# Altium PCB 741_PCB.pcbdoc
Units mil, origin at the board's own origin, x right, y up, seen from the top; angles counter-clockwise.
Board outline 3300 x 2250 mil, 2 copper layers (Top Layer, Bottom Layer); 36 components, 26 nets, 111 pads, 19 vias.
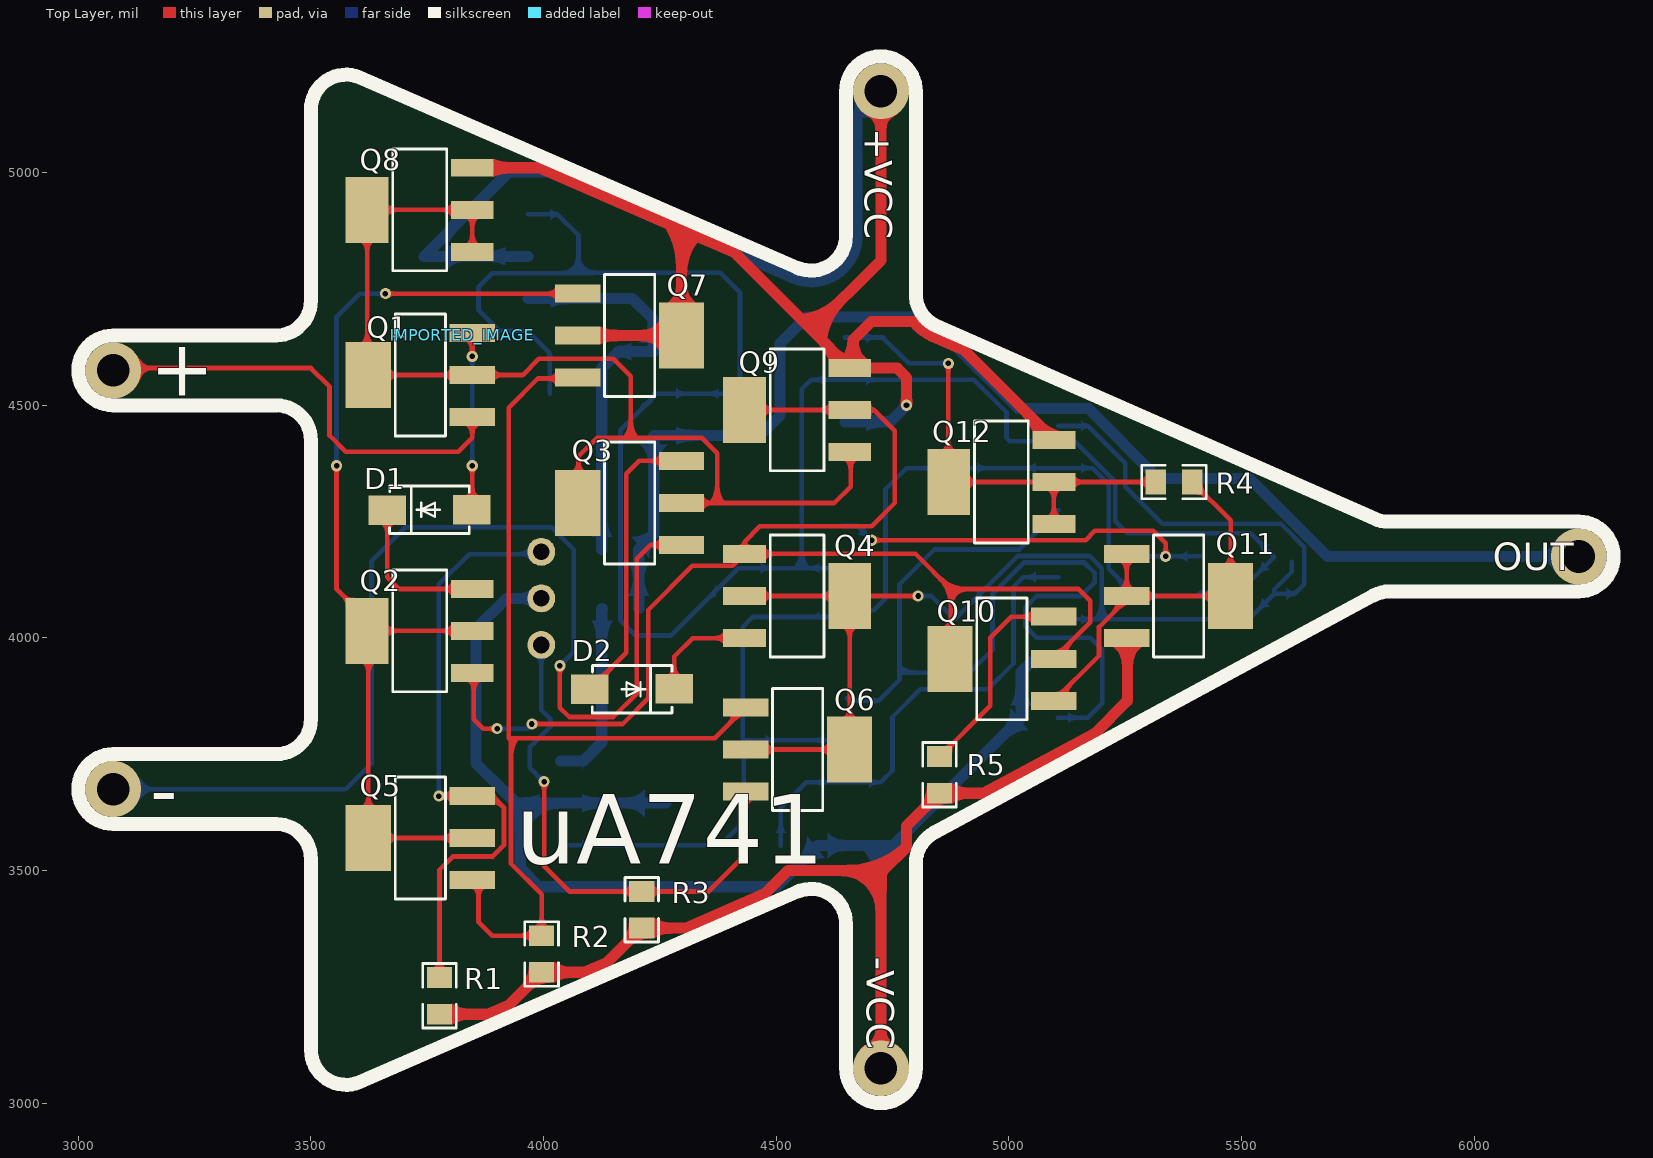
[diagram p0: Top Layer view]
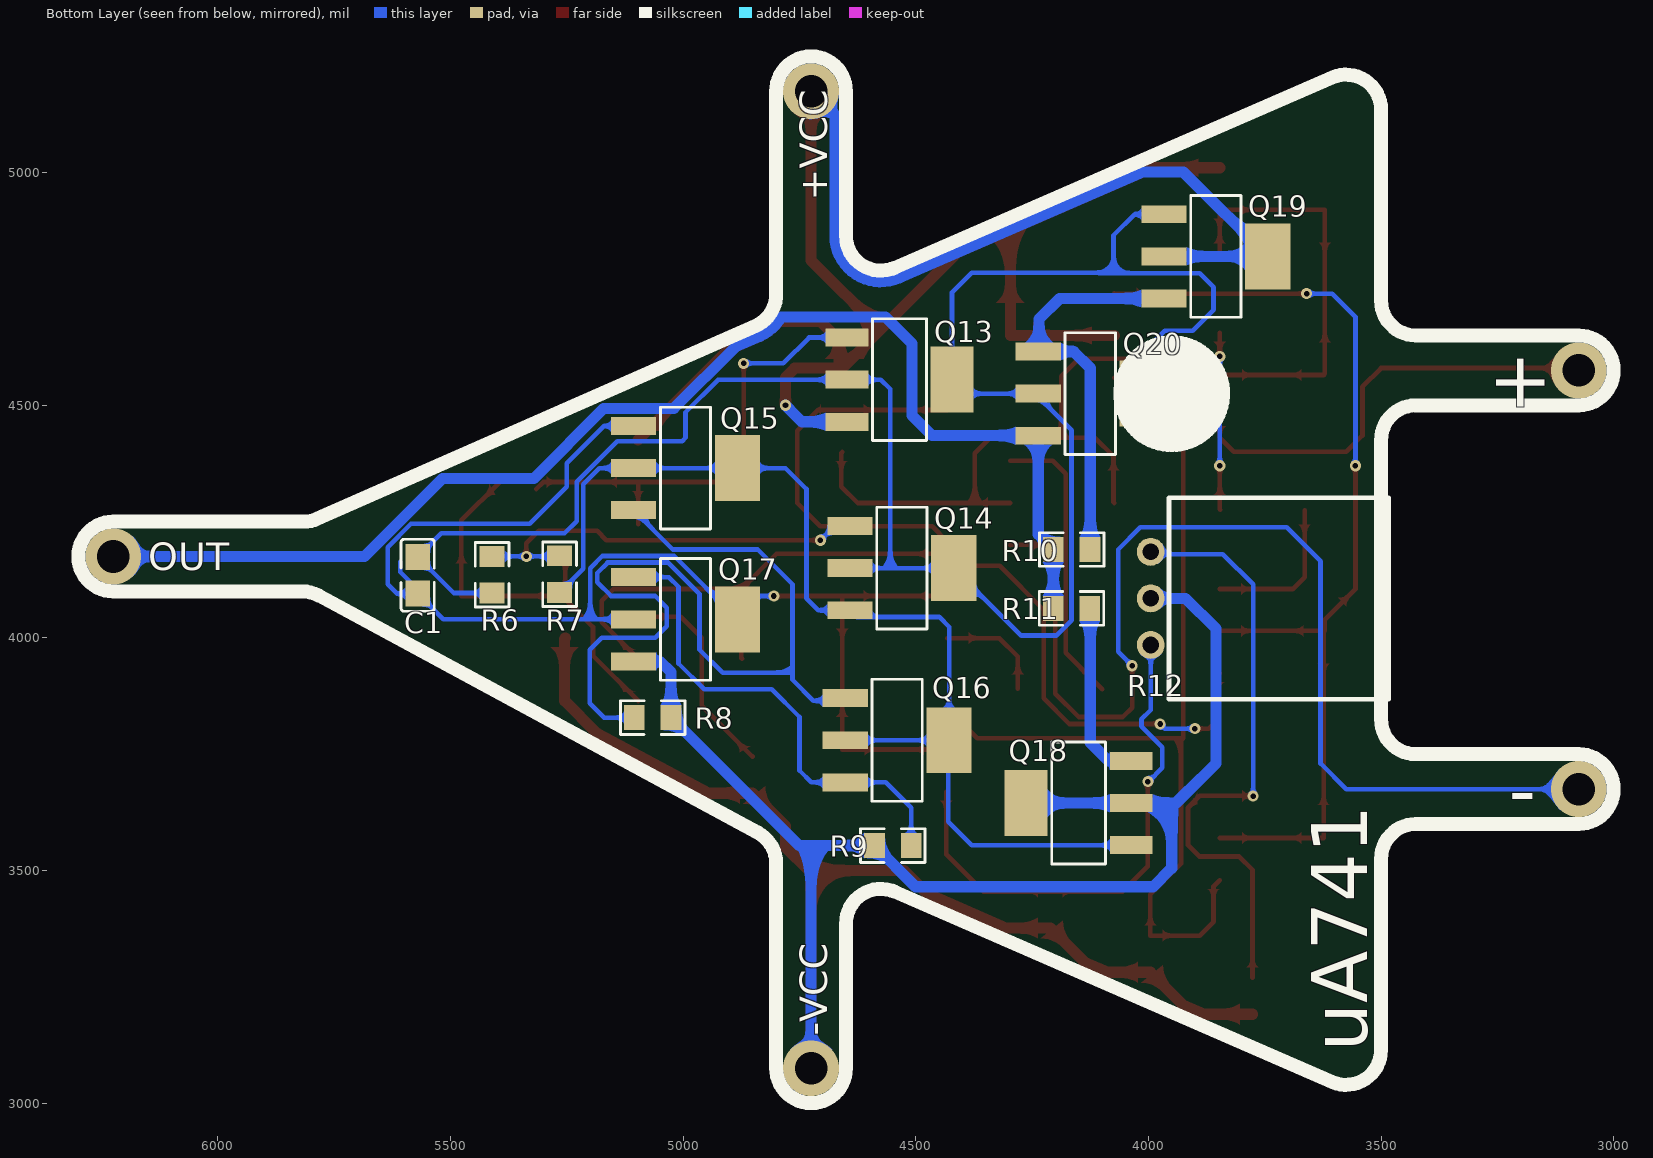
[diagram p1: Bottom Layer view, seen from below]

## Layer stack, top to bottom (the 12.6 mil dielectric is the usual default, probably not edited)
Top Layer: signal copper (thickness not stored)
Dielectric: dielectric 12.6, FR-4, Dk 4.8
Bottom Layer: signal copper (thickness not stored)

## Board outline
4844.79,4670.29 5785.57,4256.35 ccw(c5815.77,4325) 5815.77,4250 6225,4250 cw(c6225,4175) 6300,4175 cw(c6225,4175) 6225,4100 5818.96,4100 ccw(c5818.96,4025) 5783.32,4090.99 4839.36,3581.26 ccw(c4875,3515.26) 4800,3515.26 4800,3075 cw(c4725,3075) 4725,3000 cw(c4725,3075) 4650,3075 4650,3385.61 ccw(c4575,3385.61) 4545.1,3454.39 3604.91,3045.61 cw(c3575.01,3114.39) 3500.01,3114.39 3500.01,3525 ccw(c3425.01,3525) 3425.01,3600 3075,3600 cw(c3075,3675) 3000,3675 cw(c3075,3675) 3075,3750 3425,3750 ccw(c3425,3825) 3500,3825 3500,4425 ccw(c3425,4425) 3425,4500 3075,4500 cw(c3075,4575) 3000,4575 cw(c3075,4575) 3075,4650 3425,4650 ccw(c3425,4725) 3500,4725 3500,5135.61 cw(c3575,5135.61) 3604.9,5204.39 4545.1,4795.61 ccw(c4575,4864.39) 4650,4864.39 4650,5175 cw(c4725,5175) 4725,5250 cw(c4725,5175) 4800,5175 4800,4738.94 ccw(c4875,4738.94)

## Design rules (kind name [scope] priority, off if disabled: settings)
BoardOutlineClearance copperThickness1oz [All] p0: genericclearance=10 ignorepadtopadclearanceinfootprint=FALSE except(0: Arc-SplitContinuation Track-SplitContinuation SMDPad-SplitContinuation THPad-SplitContinuation Via-SplitContinuation Fill-SplitContinuation Poly-SplitContinuation Region-SplitContinuation Text-SplitContinuation; 6: Track-CutoutEdge SMDPad-CutoutEdge THPad-CutoutEdge Via-CutoutEdge Region-CutoutEdge; 11.8: Track-OutlineEdge SMDPad-OutlineEdge THPad-OutlineEdge Via-OutlineEdge Fill-OutlineEdge Region-OutlineEdge Poly-OutlineEdge Text-OutlineEdge Fill-CutoutEdge)
BoardOutlineClearance copperThickness2oz [All] p0: genericclearance=10 ignorepadtopadclearanceinfootprint=FALSE except(0: Arc-SplitContinuation Track-SplitContinuation SMDPad-SplitContinuation THPad-SplitContinuation Via-SplitContinuation Fill-SplitContinuation Poly-SplitContinuation Region-SplitContinuation Text-SplitContinuation; 6: Track-CutoutEdge SMDPad-CutoutEdge THPad-CutoutEdge Via-CutoutEdge Region-CutoutEdge; 11.8: Track-OutlineEdge SMDPad-OutlineEdge THPad-OutlineEdge Via-OutlineEdge Fill-OutlineEdge Region-OutlineEdge Poly-OutlineEdge Text-OutlineEdge Fill-CutoutEdge)
Clearance copperThickness1oz [(InNet('IN+') OR InNet('$1N519') OR InNet('$1N1834') OR InNet('$1N2546') OR InNet('$1N1895') OR InNet('$1N1839') OR InNet('$1N1919') OR InNet('$1N1914') OR InNet('OFFSET2') OR InNet('$1N1844') OR InNet('IN-') OR InNet('OFFSET1') OR InNet('VCC+') OR InNet('$1N2407') OR InNet('$1N2205') OR InNet('VCC-') OR InNet('$1N2269') OR InNet('$1N2565') OR InNet('$1N2520') OR InNet('$1N2487') OR InNet('$1N2501') OR InNet('$1N2714') OR InNet('OUT') OR InNet('$1N3714') OR InNet('$1N3732') OR InNet('$1N2679'))] p1: gap=7 ignorepadtopadclearanceinfootprint=FALSE except(4: Track-Track; 6: Track-SMDPad SMDPad-SMDPad Track-THPad SMDPad-THPad THPad-THPad Track-Via SMDPad-Via THPad-Via Via-Via SMDPad-Fill THPad-Fill Via-Fill Fill-Fill Track-Region SMDPad-Region THPad-Region Via-Region Region-Region Track-Poly SMDPad-Poly THPad-Poly Via-Poly Fill-Poly Region-Poly Poly-Poly Track-Text SMDPad-Text THPad-Text Via-Text Fill-Text Region-Text Poly-Text Text-Text; 6.9: Track-Hole SMDPad-Hole THPad-Hole Via-Hole Fill-Hole Region-Hole Poly-Hole Text-Hole Sheet-Hole; 11.8: Track-Fill Fill-Region Track-Sheet SMDPad-Sheet THPad-Sheet Via-Sheet Fill-Sheet Region-Sheet Poly-Sheet Text-Sheet)
Clearance copperThickness2oz [All] p1: gap=7 ignorepadtopadclearanceinfootprint=FALSE except(6: Track-SMDPad SMDPad-SMDPad Track-THPad SMDPad-THPad THPad-THPad Track-Via SMDPad-Via THPad-Via Via-Via SMDPad-Fill THPad-Fill Via-Fill Fill-Fill Track-Region SMDPad-Region THPad-Region Via-Region Region-Region Track-Poly SMDPad-Poly THPad-Poly Via-Poly Fill-Poly Region-Poly Poly-Poly Track-Text SMDPad-Text THPad-Text Via-Text Fill-Text Region-Text Poly-Text Text-Text; 6.9: Track-Hole SMDPad-Hole THPad-Hole Via-Hole Fill-Hole Region-Hole Poly-Hole Text-Hole Sheet-Hole; 8: Track-Track; 11.8: Track-Fill Fill-Region Track-Sheet SMDPad-Sheet THPad-Sheet Via-Sheet Fill-Sheet Region-Sheet Poly-Sheet Text-Sheet)
DiffPairsRouting differentialPair [All] p1: maxuncoupledlength=10 minlimit=6 maxlimit=6 mostfreqgap=6 toplayer_minwidth=5 toplayer_prefwidth=10 toplayer_maxwidth=100 bottomlayer_minwidth=5 bottomlayer_prefwidth=10 bottomlayer_maxwidth=100
PasteMaskExpansion pasteMaskExpansion [All] p1: expansion=0
PlaneConnect innerPlane [All] p1: planeconnectstyle=Relief reliefexpansion=20 reliefentries=4 reliefconductorwidth=10 reliefairgap=10
PolygonConnect copperRegion [All] p1: connectstyle=Relief reliefentries=4 reliefconductorwidth=10 polygonreliefangle="90 Angle" airgapwidth=10
RoutingVias viaSize [All] p1: viastyle="Through Hole" holewidth=12.0078 minholewidth=11.811 maxholewidth=248.0314 width=24.0158 minwidth=19.685 maxwidth=393.7008
SolderMaskExpansion solderMaskExpansion [All] p1: useseparateexpansions=TRUE expansion=2 expansionbottom=2
Width copperThickness1oz [All] p1: maxlimit=100 minlimit=5 preferedwidth=10
Width copperThickness2oz [All] p1: maxlimit=100 minlimit=8 preferedwidth=10

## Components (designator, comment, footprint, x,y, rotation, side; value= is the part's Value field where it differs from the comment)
C1 "CC0805JRNPO9BN330" C0805 5570.63,4134.57 r90 bottom
D1 "SS24_C7420362" SMA_L4.3-W2.6-LS5.0-FD 3755,4275 r180 top
D2 "SS24_C7420362" SMA_L4.3-W2.6-LS5.0-FD 4190,3890 r0 top
IMPORTED_IMAGE "IMPORTED_IMAGE" IMPORTED_IMAGE 3825,4650 r0 top
Q1 "BCP56-16_C41375109" SOT-223-4_L6.5-W3.5-P2.30-LS7.0-BR 3735,4565 r0 top
Q2 "BCP53-16_C41375110" SOT-223-3_L6.7-W3.7-P2.30-LS7.0-BR 3733.82,4015 r0 top
Q3 "BCP56-16_C41375109" SOT-223-4_L6.5-W3.5-P2.30-LS7.0-BR 4185,4290 r0 top
Q4 "BCP53-16_C41375110" SOT-223-3_L6.7-W3.7-P2.30-LS7.0-BR 4545,4090 r180 top
Q5 "BCP56-16_C41375109" SOT-223-4_L6.5-W3.5-P2.30-LS7.0-BR 3735,3570 r0 top
Q6 "BCP56-16_C41375109" SOT-223-4_L6.5-W3.5-P2.30-LS7.0-BR 4546.18,3760 r180 top
Q7 "BCP56-16_C41375109" SOT-223-4_L6.5-W3.5-P2.30-LS7.0-BR 4185,4650 r180 top
Q8 "BCP53-16_C41375110" SOT-223-3_L6.7-W3.7-P2.30-LS7.0-BR 3733.82,4920 r0 top
Q9 "BCP53-16_C41375110" SOT-223-3_L6.7-W3.7-P2.30-LS7.0-BR 4545,4490 r0 top
Q10 "BCP56-16_C41375109" SOT-223-4_L6.5-W3.5-P2.30-LS7.0-BR 4985,3955 r0 top
Q11 "BCP56-16_C41375109" SOT-223-4_L6.5-W3.5-P2.30-LS7.0-BR 5365,4090 r180 top
Q12 "BCP53-16_C41375110" SOT-223-3_L6.7-W3.7-P2.30-LS7.0-BR 4983.82,4335 r0 top
Q13 "BCP53-16_C41375110" SOT-223-3_L6.7-W3.7-P2.30-LS7.0-BR 4535,4555 r0 bottom
Q14 "BCP56-16_C41375109" SOT-223-4_L6.5-W3.5-P2.30-LS7.0-BR 4530,4150 r0 bottom
Q15 "BCP56-16_C41375109" SOT-223-4_L6.5-W3.5-P2.30-LS7.0-BR 4995,4365 r0 bottom
Q16 "BCP56-16_C41375109" SOT-223-4_L6.5-W3.5-P2.30-LS7.0-BR 4540,3780 r0 bottom
Q17 "BCP56-16_C41375109" SOT-223-4_L6.5-W3.5-P2.30-LS7.0-BR 4995,4040 r0 bottom
Q18 "BCP53-16_C41375110" SOT-223-3_L6.7-W3.7-P2.30-LS7.0-BR 4150,3645 r180 bottom
Q19 "BCP56-16_C41375109" SOT-223-4_L6.5-W3.5-P2.30-LS7.0-BR 3855,4820 r0 bottom
Q20 "BCP56-16_C41375109" SOT-223-4_L6.5-W3.5-P2.30-LS7.0-BR 4125,4525 r0 bottom
R1 "0805W8F1001T5E" R0805 3776.19,3230.62 r90 top
R2 "0805W8F5102T5E" R0805 3995.79,3320.62 r90 top
R3 "0805W8F1001T5E" R0805 4210.79,3415.62 r90 top
R4 "0805W8F3902T5E" R0805 5355,4335 r180 top
R5 "0805W8F4701T5E" R0805 4850.94,3705.62 r90 top
R6 "0805W8F4701T5E" R0805 5410.63,4135.83 r270 bottom
R7 "0805W8F7501T5E" R0805 5265.63,4137.09 r90 bottom
R8 "0805W8F5102T5E" R0805 5065.63,3828.62 r0 bottom
R9 "0805W8F510JT5E" R0805 4549.37,3553.62 r180 bottom
R10 "0805W8F2401T5E" R0805 4165,4190 r180 bottom
R11 "0805W8F510JT5E" R0805 4165.42,4063.44 r0 bottom
R12 "3296W-1-103_C48997937" 电位器 3995,3985 r90 bottom

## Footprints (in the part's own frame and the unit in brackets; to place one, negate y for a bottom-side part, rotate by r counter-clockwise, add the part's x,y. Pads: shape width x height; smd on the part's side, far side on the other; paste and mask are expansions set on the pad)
C0805 [mm]
  rect 1.41x1.35 smd: 1(-1,0) 2(1,0)
  silkscreen extent -1.96,-0.9 1.96,0.9
IMPORTED_IMAGE [mil]
R0805 [mm]
  rect 1.133x1.377 smd: 1(-1,0) 2(1,0)
  silkscreen extent -1.76,-0.92 1.76,0.92
SMA_L4.3-W2.6-LS5.0-FD [mm]
  rect 2.046x1.62 smd: 1(-2.304,-0.009) 2(2.304,0.009)
  silkscreen extent -2.17,-1.32 2.19,1.29
SOT-223-3_L6.7-W3.7-P2.30-LS7.0-BR [mm]
  rect 2.34x0.98 smd: 1(2.87,-2.3) 2(2.87,0) 3(2.87,2.3)
  rect 2.34x3.6 smd: 4(-2.87,0)
  silkscreen extent -1.47,-3.33 1.47,3.33
SOT-223-4_L6.5-W3.5-P2.30-LS7.0-BR [mm]
  rect 2.47x0.98 smd: 1(2.835,-2.3) 2(2.835,0) 3(2.835,2.3)
  rect 2.47x3.6 smd: 4(-2.835,0)
  silkscreen extent -1.37,-3.33 1.37,3.33
电位器 [mil]
  round 60 hole 36: 1(0,0) 2(100,0) 3(200,0)
  silkscreen extent -117,-512 317,-39

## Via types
v1: diameter 24.02, hole 12.01, Top Layer to Bottom Layer, 14 vias
v2: diameter 120, hole 70, Top Layer to Bottom Layer, 5 vias

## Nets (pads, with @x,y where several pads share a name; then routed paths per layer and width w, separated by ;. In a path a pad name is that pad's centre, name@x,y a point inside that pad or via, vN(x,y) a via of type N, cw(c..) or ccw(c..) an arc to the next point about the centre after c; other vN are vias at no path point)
$1N519: Q1.2 Q1.4 Q3.2 Q3.4 Q8.1 Q8.2 Q8.4 Q9.1 | length 2389.1
  Top Layer w10: Q8.1 Q8.2 Q8.4 3620.83,4567.56 Q1.4 Q1.2 3955,4565 3990,4600 4150,4600 4187.5,4562.5 4187.5,4432.11 4189.61,4430 ; Q3.4 4075,4291.61 4075,4390 4115,4430 4189.61,4430 ; Q3.2 4372.9,4290 ; Q9.1 4660,4397.44 4660,4325 4625,4290 4372.9,4290 ; 4189.61,4430 4340,4430 4372.9,4397.1 4372.9,4290
$1N1834: D1.1 Q1.3 | length 380.6
  Top Layer w10: D1.1 3846.61,4276.27 v1(3846.61,4370) ; v1(3846.61,4605) Q1.3
  Bottom Layer w10: v1(3846.61,4370) v1(3846.61,4605)
$1N1839: D1.2 Q2.3 | length 337.3
  Top Layer w10: D1.2 3664.3,4130.7 3690,4105 3846.26,4105 Q2.3
$1N1844: Q2.2 Q2.4 Q5.2 Q5.4 Q7.1 | length 2136.9
  Top Layer w10: v1(3555,4370) 3555,4105 3620.83,4039.17 Q2.4 ; v1(3660,4740) 4072.84,4740 Q7.1 ; Q5.2 Q5.4 3623.39,4012.44 Q2.4 ; Q2.2 Q2.4
  Bottom Layer w10: v1(3555,4370) 3555,4690 3605,4740 v1(3660,4740)
$1N1895: C1.1 Q4.2 Q4.4 Q6.2 Q6.4 Q15.1 Q17.2 Q17.4 | length 2908.2
  Top Layer w10: Q4.2 Q4.4 ; Q6.2 Q6.4 4657.99,3760.2 Q4.4 ; v1(4805,4090) Q4.4
  Bottom Layer w10: v1(4805,4090) 4833.39,4090 Q17.4 5019.37,4175.98 5174.02,4175.98 5200,4150 5200,4040.02 ; Q17.2 5200.02,4040 ; Q15.1 5169.45,4455.55 5250,4375 5250,4325 5330,4245 5585,4245 5635,4195 5635,4115 5615,4095 5570.83,4095 C1.1 ; 5608.19,4163.53 5608.19,4141.63 5570.63,4104.07 C1.1 ; 5200.02,4040 5515.43,4040 C1.1
$1N1914: D2.2 Q4.3 | length 237.3
  Top Layer w10: D2.2 4280.7,3960 4320.15,3999.45 Q4.3
$1N1919: D2.1 Q3.3 | length 626
  Top Layer w10: D2.1 4177.5,3967.84 4177.5,4352.5 4205.55,4380.55 Q3.3
$1N2205: Q10.3 R5.2 | length 455.7
  Top Layer w10: R5.2 4960,3854.05 4960,4000 5005.55,4045.55 Q10.3
$1N2269: Q12.1 Q12.2 Q12.4 Q13.1 R4.2 | length 1041.9
  Top Layer w10: v1(4870,4590) 4870,4335.83 Q12.4 Q12.2 ; Q12.1 Q12.2 ; R4.2@5315.63,4320 5300.63,4335 Q12.2
  Bottom Layer w10: Q13.1 4729.45,4645.55 4785,4590 v1(4870,4590)
$1N2407: Q10.1 Q11.1 Q11.2 Q11.4 R4.1 | length 883.3
  Top Layer w10: Q10.1 5193.78,3961.62 5193.78,4023.29 5253.39,4082.9 Q11.2 ; Q11.1 Q11.2 ; R4.1 5476.61,4252.76 Q11.4 Q11.2
$1N2487: Q15.3 Q16.1 R8.2 | length 1988.8
  Bottom Layer w10: Q16.1 4657.16,3865 4720,3865 4765,3910 4765,3920.79 ; R8.2 5170,3828.62 5200.69,3859.31 5200.69,3974.31 5175,4000 5060,4000 5035,4025 5035,4065 5060,4090 5155,4090 5185,4120 5185,4139.47 5162.5,4161.97 5031.97,4161.97 4965,4095 4965,3975 4915,3925 4769.21,3925 4765,3920.79 ; Q15.3 5022.16,4190 4840,4190 4765,4115 4765,3920.79
$1N2501: Q16.3 Q17.1 R9.2 | length 1047.3
  Bottom Layer w10: R9.2 4510,3635 4564.45,3689.45 Q16.3 4724.45,3689.45 4750,3715 4750,3830 4810,3890 4955,3890 5010,3945 5010,4110 5030.55,4130.55 Q17.1
$1N2520: Q14.3 Q15.2 Q15.4 Q16.2 Q16.4 Q18.1 R7.1 | length 2389.7
  Bottom Layer w10: Q18.1 4379.45,3554.45 4430,3605 4430,3778.39 Q16.4 ; Q16.2 Q16.4 ; R7.1 5215,4148.35 5215,4330 5180,4365 Q15.2 Q15.4 4780,4365 4735,4320 4735,4085 4709.45,4059.45 Q14.3 4627.16,4045 4450,4045 4428.39,4023.39 Q16.4
$1N2546: C1.2 Q13.2 Q13.4 Q14.2 Q14.4 Q19.1 Q20.2 Q20.4 R6.2 | length 4421.7
  Bottom Layer w10: Q19.1 4029.45,4910.55 4075,4865 4075,4783.9 ; Q20.4 4013.39,4611.61 3965,4660 3905,4660 3860,4705 3860,4753.9 3890,4783.9 4075,4783.9 ; Q14.2 4555.53,4150 ; R6.2 5493.15,4096.46 C1.2 5519.57,4225 5255,4225 5229.02,4250.98 5229.02,4335.81 5141.89,4422.93 5002.07,4422.93 4995,4430 4995,4485 4925,4555 Q13.2 4575,4555 4555,4535 4555,4150.53 4555.53,4150 ; 4075,4783.9 4075.96,4783.9 4077.06,4785 4380,4785 4422.01,4742.99 Q13.4 4392.01,4525 Q20.2 4236.61,4517.9 4165.16,4446.45 4165.16,4038.14 4198.3,4005 4273.39,4005 Q14.4 4555.53,4150
$1N2565: Q14.1 R6.1 R7.2 | length 900.8
  Top Layer w10: v1(4705,4210) 5165,4210 5185,4230 5310,4230 5336.97,4203.03 v1(5336.97,4175.2)
  Bottom Layer w10: Q14.1 4674.45,4240.55 v1(4705,4210) ; R7.2 5266.89,4175.2 v1(5336.97,4175.2) R6.1
$1N2679: Q19.3 Q20.1 R10.2 | length 873.5
  Bottom Layer w24: Q19.3 4190.55,4729.45 4235,4685 4235,4617.16 Q20.1 4160.55,4615.55 4125,4580 4125,4190.63 R10.2
$1N2714: Q18.3 R11.1 | length 393.2
  Bottom Layer w24: Q18.3 4085.55,3735.55 4125,3775 4125,4062.38 R11.1
$1N3714: Q2.1 Q4.1 Q9.2 Q9.4 Q10.2 Q10.4 | length 2931.2
  Top Layer w10: Q2.1 3850,3921.26 3850,3825 3870,3805 v1(3900,3805) ; v1(3975,3815) 4170,3815 4225,3870 4225,4060 4320,4155 4406.46,4155 Q4.1 ; Q9.4 Q9.2 4710,4490 4755,4445 4755,4290 4705,4240 4465,4240 4432.01,4207.01 Q4.1 ; Q10.4 4875,3956.61 4875,4105 ; Q10.2 5175,4033.39 5175,4080 5150,4105 4875,4105 ; Q4.1 4799.45,4180.55 4875,4105
  Bottom Layer w10: v1(3900,3805) 3965,3805 v1(3975,3815)
$1N3732: Q5.1 Q6.1 Q7.3 R2.2 | length 2119.8
  Top Layer w10: Q5.1 3860,3466.06 3860,3390 3890.01,3359.99 R2.2 3995.79,3449.21 3930,3515 3930,3779.05 3925,3784.05 ; Q7.3 4071.44,4557.5 3987.5,4557.5 3925,4495 3925,3784.05 ; Q6.1 4368.07,3784.05 3925,3784.05
IN+: Q1.1 | length 966.6
  Top Layer w10: v2(3075,4575) 3080,4580 3500,4580 3540,4540 3540,4435 3575,4400 3816.61,4400 3846.61,4430 Q1.1
IN-: Q3.1 | length 2443.2
  Top Layer w10: v1(4035,3940) 4035,3850 4055,3830 4150,3830 4200,3880 4200,4170 4230,4200 4296.06,4200 Q3.1
  Bottom Layer w10: v2(3075,3675) 3575,3675 3630,3730 3630,4165 3702.5,4237.5 4017.5,4237.5 4065,4190 4065,3970 v1(4035,3940)
OFFSET1: Q5.3 R1.2 R12.3 | length 1327.1
  Top Layer w10: v1(3775,3660) 3775.55,3660.55 Q5.3 3889.45,3660.55 3915,3635 3915,3554.94 3890.06,3530 3805,3530 3776.19,3501.19 R1.2
  Bottom Layer w10: v1(3775,3660) 3775,4115 3840,4180 3990,4180 R12.3
OFFSET2: Q6.3 R3.2 R12.1 | length 1140.5
  Top Layer w10: v1(4001.22,3691.22) 4001.22,3508.78 4055.01,3454.99 R3.2 4355,3455 4434.57,3534.57 Q6.3
  Bottom Layer w10: R12.1 3995,3845 4015,3825 4015,3810 3970,3765 3970,3720.77 3999.55,3691.22 v1(4001.22,3691.22)
OUT: Q20.3 R10.1 R11.2 | length 2778
  Bottom Layer w24: R11.2 4204.37,4063.86 R10.1 4236.61,4222.24 Q20.3 4237.16,4435 4465,4435 4508.03,4478.03 4508.03,4633.03 4565,4690 4789.16,4690 ccw(c4875,4738.94) 4835.2,4648.5 4887.93,4625.3 5020.4,4492.83 5170.85,4492.83 5321.02,4342.66 5517.06,4342.66 5684.72,4175 v2(6225,4175)
VCC+: Q7.2 Q7.4 Q8.3 Q9.3 Q12.3 Q13.3 Q19.2 Q19.4 | length 4588.1
  Top Layer w24: Q8.3 3991.02,5010.55 4299.77,4876.31 ; Q7.2 Q7.4 4296.61,4873.15 4299.77,4876.31 ; v2(4725,5175) 4725,4811.65 4575.95,4662.59 ; v1(4780,4500) 4780,4560 4760,4580 4658.54,4580 Q9.3 ; Q12.3 4904.24,4618.12 4835.2,4648.5 cw(c4875,4738.94) 4795.69,4680 4705,4680 4665,4640 4665,4587.56 Q9.3 ; 4299.77,4876.31 4410.28,4828.26 4575.95,4662.59 ; 4575.95,4662.59 Q9.3
  Bottom Layer w24: Q19.2 Q19.4 3925.08,5001.69 4011.39,5001.69 4535.6,4773.77 ccw(c4575,4864.39) 4673.81,4864.39 4673.81,5123.81 v2(4725,5175) ; Q13.3 4744.45,4464.45 v1(4780,4500)
VCC-: Q11.3 Q17.3 Q18.2 Q18.4 R1.1 R2.1 R3.1 R5.1 R8.1 R9.1 R12.2 | length 5253.2
  Top Layer w24: R1.1 3880.15,3191.25 3925.51,3210.97 R2.1 4087.15,3281.25 4137.82,3303.28 R3.1 4305.65,3376.25 4474.78,3449.78 4525,3500 4730,3500 ; v2(4725,3075) 4725,3495 4730,3500 ; Q11.3 5255,3997.84 5255,3865 5184.91,3794.91 4946.64,3666.25 R5.1 4780,3595.31 4780,3550 4730,3500
  Bottom Layer w24: R12.2 3920,4085 3855,4020 3855,3730 3940,3645 3949.88,3645 ; Q18.4 Q18.2 3949.88,3645 ; v2(4725,3075) 4725,3550.49 4721.88,3553.62 ; Q17.3 5049.45,3949.45 5026.26,3926.26 R8.1 4751.26,3553.62 4721.88,3553.62 ; 3949.88,3645 3950,3644.88 3950,3505 3990,3465 4500.12,3465 R9.1 4721.88,3553.62

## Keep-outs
Board Outline Layer:
  the board outline again, w10

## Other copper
Top Layer:
  region net $1N2407: 5471.61,4175.87 5481.61,4175.87 ccw(c5500.36,4175.87) 5489.11,4160.87 5464.11,4160.87 ccw(c5452.86,4175.87)
  region net $1N2407: 5421.97,4314.47 5419.71,4302.59 ccw(c5403.8,4281.38) 5403.8,4307.89 5416.66,4330.38 ccw(c5443.18,4330.38)
  region net $1N2407: 5412.99,4085 5412.99,4095 ccw(c5412.99,4113.75) 5427.99,4102.5 5427.99,4077.5 ccw(c5412.99,4066.25)
  region net $1N2407: 5317.01,4095 5317.01,4085 ccw(c5317.01,4066.25) 5302.01,4077.5 5302.01,4102.5 ccw(c5317.01,4113.75)
  region net $1N2565: 5331.97,4191.55 5341.97,4191.55 5342.06,4190.41 5342.32,4189.28 5343.22,4187.06 5344.51,4184.99 5345.98,4183.14 5327.97,4183.14 5329.44,4184.99 5330.72,4187.06 5331.63,4189.28 5331.88,4190.41
  region net VCC-: 5267,3944.16 5243,3944.16 ccw(c5198,3944.16) 5225,3980.16 5285,3980.16 ccw(c5312,3944.16)
  region net $1N2407: 5258.39,4146.26 5248.39,4146.26 ccw(c5229.64,4146.26) 5240.89,4161.26 5265.89,4161.26 ccw(c5277.14,4146.26)
  region net $1N2407: 5248.39,4124.29 5258.39,4124.29 ccw(c5277.14,4124.29) 5265.89,4109.29 5240.89,4109.29 ccw(c5229.64,4124.29)
  region net $1N2407: 5240.38,4062.82 5220.81,4057.39 ccw(c5198.73,4079.47) 5228.7,4070.71 5253.7,4070.71 ccw(c5262.46,4040.74)
  region net $1N2269: 5278.34,4330 5278.34,4340 ccw(c5278.34,4358.75) 5293.34,4347.5 5293.34,4322.5 ccw(c5278.34,4311.25)
  region net $1N2269: 5157.87,4340 5157.87,4330 ccw(c5157.87,4311.25) 5142.87,4322.5 5142.87,4347.5 ccw(c5157.87,4358.75)
  region net $1N2407: 5116.72,3891.63 5136.29,3897.06 ccw(c5158.37,3874.98) 5128.4,3883.74 5103.4,3883.74 ccw(c5094.64,3913.71)
  region net $1N3714: 5116.72,3982.18 5136.29,3987.61 ccw(c5158.37,3965.53) 5128.4,3974.29 5103.4,3974.29 ccw(c5094.64,4004.26)
  region net $1N2269: 5101.81,4300.71 5091.81,4300.71 ccw(c5073.06,4300.71) 5084.31,4315.71 5109.31,4315.71 ccw(c5120.56,4300.71)
  region net $1N2269: 5091.81,4278.74 5101.81,4278.74 ccw(c5120.56,4278.74) 5109.31,4263.74 5084.31,4263.74 ccw(c5073.06,4278.74)
  region net $1N2205: 5032.99,4040.55 5032.99,4050.55 ccw(c5032.99,4069.3) 5047.99,4058.05 5047.99,4033.05 ccw(c5032.99,4021.8)
  region net VCC+: 5030.19,4475.2 5075.55,4463.78 ccw(c5128.54,4516.77) 5107.52,4444.84 5050.75,4444.84 ccw(c4961.63,4406.63)
  region net $1N2269: 4931.89,4340 4931.89,4330 ccw(c4931.89,4311.25) 4916.89,4322.5 4916.89,4347.5 ccw(c4931.89,4358.75)
  region net $1N2565: 4721.35,4215 4721.35,4205 4720.21,4204.91 4719.08,4204.66 4716.86,4203.75 4714.79,4202.47 4712.94,4200.99 4712.94,4219.01 4714.79,4217.53 4716.86,4216.25 4719.08,4215.34 4720.21,4215.09
  region net $1N2205: 4871.47,3772.58 4883.35,3770.32 ccw(c4904.56,3754.41) 4878.05,3754.41 4855.56,3767.28 ccw(c4855.56,3793.8)
  region net VCC-: 4914.05,3678.25 4914.05,3654.25 ccw(c4914.05,3586.15) 4878.05,3643.95 4878.05,3688.54 ccw(c4914.05,3746.34)
  region net $1N3714: 4870,4040.87 4880,4040.87 ccw(c4898.75,4040.87) 4887.5,4025.87 4862.5,4025.87 ccw(c4851.25,4040.87)
  region net $1N2269: 4865,4420.87 4875,4420.87 ccw(c4893.75,4420.87) 4882.5,4405.87 4857.5,4405.87 ccw(c4846.25,4420.87)
  region net $1N2269: 4875,4573.65 4865,4573.65 4864.91,4574.79 4864.66,4575.92 4863.75,4578.14 4862.47,4580.21 4860.99,4582.06 4879.01,4582.06 4877.53,4580.21 4876.25,4578.14 4875.34,4575.92 4875.09,4574.79
  region net $1N3714: 4907.07,4110 cw(c4907.07,4182.43) 4855.86,4131.21 4848.79,4124.14 cw(c4797.57,4072.93) 4870,4072.93 4880,4070 cw(c4910,4070) 4910,4100
  region net VCC-: 4832.89,3631.22 4811.1,3643.38 ccw(c4760.19,3681.57) 4823.83,3681.57 4871.07,3643.95 ccw(c4871.07,3580.31)
  region net VCC+: 4768,4514.41 4792,4514.41 4792.01,4500 4767.99,4500
  region net $1N1895: 4788.65,4085 4788.65,4095 4789.79,4095.09 4790.92,4095.34 4793.14,4096.25 4795.21,4097.53 4797.06,4099.01 4797.06,4080.99 4795.21,4082.47 4793.14,4083.75 4790.92,4084.66 4789.79,4084.91
  region net VCC+: 4737,5093.31 4713,5093.31 4712.81,5097.69 4712.26,5101.51 4711.37,5104.85 4710.16,5107.77 4708.67,5110.34 4706.91,5112.63 4704.91,5114.71 4702.69,5116.65 4697.69,5120.38 4692.12,5124.37 4689.17,5126.63 4686.16,5129.16 4683.09,5132.03 4680,5135.31 4770,5135.31 4766.91,5132.03 4763.84,5129.16 4760.83,5126.63 4757.88,5124.37 4752.31,5120.38 4747.31,5116.65 4745.09,5114.71 4743.09,5112.63 4741.33,5110.34 4739.84,5107.77 4738.63,5104.85 4737.74,5101.51 4737.19,5097.69
  region net VCC-: 4713,3156.69 4737,3156.69 4737.19,3152.31 4737.74,3148.49 4738.63,3145.15 4739.84,3142.23 4741.33,3139.66 4743.09,3137.37 4745.09,3135.29 4747.31,3133.35 4752.31,3129.62 4757.88,3125.63 4760.83,3123.37 4763.84,3120.84 4766.91,3117.97 4770,3114.69 4680,3114.69 4683.09,3117.97 4686.16,3120.84 4689.17,3123.37 4692.12,3125.63 4697.69,3129.62 4702.69,3133.35 4704.91,3135.29 4706.91,3137.37 4708.67,3139.66 4710.16,3142.23 4711.37,3145.15 4712.26,3148.49 4712.81,3152.31
  region net $1N3714: 4710,4495 4710,4485 ccw(c4711.76,4477.5) 4704.05,4477.5 4704.05,4502.5 ccw(c4711.76,4502.5)
  region net VCC+: 4653,4635.84 4677,4635.84 ccw(c4722,4635.84) 4695,4599.84 4635,4599.84 ccw(c4608,4635.84)
  region net $1N519: 4665,4365.16 4655,4365.16 ccw(c4636.25,4365.16) 4647.5,4380.16 4672.5,4380.16 ccw(c4683.75,4365.16)
  region net $1N1895: 4652.99,3845.87 4662.99,3845.87 ccw(c4681.74,3845.87) 4670.49,3830.87 4645.49,3830.87 ccw(c4634.24,3845.87)
  region net $1N1895: 4662.99,4004.13 4652.99,4004.13 ccw(c4634.24,4004.13) 4645.49,4019.13 4670.49,4019.13 ccw(c4681.74,4004.13)
  region net VCC-: 4737,3418.25 4737.39,3490.55 4771.51,3558.49 cw(c4653.03,3686.24) 4653.03,3512 4641,3488 cw(c4641,3416) 4713,3416
  region net VCC+: 4591.37,4630.2 4636.73,4618.78 ccw(c4689.72,4671.77) 4668.7,4599.84 4611.93,4599.84 ccw(c4522.81,4561.63)
  region net $1N3714: 4493.07,4185.55 4493.07,4175.55 ccw(c4493.07,4156.8) 4478.07,4168.05 4478.07,4193.05 ccw(c4493.07,4204.3)
  region net $1N1895: 4594.17,3755 4594.17,3765 ccw(c4594.17,3783.75) 4609.17,3772.5 4609.17,3747.5 ccw(c4594.17,3736.25)
  region net $1N1895: 4498.19,3765 4498.19,3755 ccw(c4498.19,3736.25) 4483.19,3747.5 4483.19,3772.5 ccw(c4498.19,3783.75)
  region net $1N1895: 4493.07,4095 4493.07,4085 ccw(c4493.07,4066.25) 4478.07,4077.5 4478.07,4102.5 ccw(c4493.07,4113.75)
  region net $1N1895: 4596.93,4085 4596.93,4095 ccw(c4596.93,4113.75) 4611.93,4102.5 4611.93,4077.5 ccw(c4596.93,4066.25)
  region net $1N3714: 4493.07,4495 4493.07,4485 ccw(c4493.07,4466.25) 4478.07,4477.5 4478.07,4502.5 ccw(c4493.07,4513.75)
  region net $1N3714: 4596.93,4485 4596.93,4495 ccw(c4596.93,4513.75) 4611.93,4502.5 4611.93,4477.5 ccw(c4596.93,4466.25)
  region net VCC+: 4626.86,4730.48 cw(c4542.01,4815.33) 4558.98,4696.53 4575.95,4662.59 4609.89,4645.62 cw(c4728.68,4628.65) 4643.83,4713.51
  region net OFFSET2: 4439.57,3635.16 4429.57,3635.16 ccw(c4410.82,3635.16) 4422.07,3650.16 4447.07,3650.16 ccw(c4458.32,3635.16)
  region net $1N3714: 4427.01,4207.01 4437.01,4207.01 ccw(c4444.51,4207.35) 4444.51,4199.84 4419.51,4199.84 ccw(c4419.51,4207.35)
  region net $1N3732: 4414.46,3823.37 4394.89,3817.94 ccw(c4372.81,3840.02) 4402.78,3831.26 4427.78,3831.26 ccw(c4436.54,3801.29)
  region net $1N1914: 4370.95,3994.45 4370.95,4004.45 ccw(c4370.95,4023.2) 4385.95,4011.95 4385.95,3986.95 ccw(c4370.95,3975.7)
  region net $1N519: 4360.23,4295 4360.23,4285 ccw(c4360.23,4266.25) 4345.23,4277.5 4345.23,4302.5 ccw(c4360.23,4313.75)
  region net $1N519: 4367.9,4325 cw(c4317.9,4325) 4357.9,4295 4372.9,4290 4387.9,4295 cw(c4427.9,4325) 4377.9,4325
  region net VCC+: 4284.61,4756.87 4308.61,4756.87 ccw(c4353.61,4756.87) 4326.61,4720.87 4266.61,4720.87 ccw(c4239.61,4756.87)
  region net OFFSET2: 4252.9,3460 4252.9,3450 ccw(c4252.9,3431.25) 4237.9,3442.5 4237.9,3467.5 ccw(c4252.9,3478.75)
  region net $1N1914: 4275.7,3937.26 4285.7,3937.26 ccw(c4304.45,3937.26) 4293.2,3922.26 4268.2,3922.26 ccw(c4256.95,3937.26)
  region net IN-: 4232.99,4195 4232.99,4205 ccw(c4232.99,4223.75) 4247.99,4212.5 4247.99,4187.5 ccw(c4232.99,4176.25)
  region net VCC-: 4273.9,3388.25 4273.9,3364.25 ccw(c4273.9,3296.15) 4237.9,3353.95 4237.9,3398.54 ccw(c4273.9,3456.34)
  region net $1N1919: 4232.99,4375.55 4232.99,4385.55 ccw(c4232.99,4404.3) 4247.99,4393.05 4247.99,4368.05 ccw(c4232.99,4356.8)
  region net VCC+: 4158.01,4662 4158.01,4638 ccw(c4158.01,4545.48) 4122.01,4630.71 4122.01,4669.29 ccw(c4158.01,4754.52)
  region net VCC+: 4211.99,4638 4211.99,4662 ccw(c4211.99,4707) 4247.99,4680 4247.99,4620 ccw(c4211.99,4593)
  region net VCC-: 4192.74,3341.22 4170.96,3353.38 ccw(c4120.04,3391.57) 4183.68,3391.57 4230.92,3353.95 ccw(c4230.92,3290.31)
  region net $1N519: 4192.5,4465 ccw(c4242.5,4465) 4202.5,4435 4189.61,4430 4172.5,4435 ccw(c4132.5,4465) 4182.5,4465
  region net VCC+: 4308.61,4787.38 cw(c4408.16,4787.38) 4330.62,4849.81 4299.77,4876.31 4262.6,4879.39 cw(c4122.45,4797.82) 4284.61,4797.82
  region net $1N1919: 4132.01,3929.41 4149.52,3932.79 ccw(c4234.96,3847.35) 4139.58,3921.52 4118.69,3921.52 ccw(c4109.93,3951.49)
  region net OFFSET2: 4168.68,3449.99 4168.68,3459.99 ccw(c4168.68,3478.74) 4183.68,3467.49 4183.68,3442.49 ccw(c4168.68,3431.24)
  region net $1N519: 4070,4375.87 4080,4375.87 ccw(c4098.75,4375.87) 4087.5,4360.87 4062.5,4360.87 ccw(c4051.25,4375.87)
  region net $1N3714: 3991.35,3820 3991.35,3810 3990.21,3809.91 3989.08,3809.66 3986.86,3808.75 3984.79,3807.47 3982.94,3805.99 3982.94,3824.01 3984.79,3822.53 3986.86,3821.25 3989.08,3820.34 3990.21,3820.09
  region net VCC-: 4058.9,3293.25 4058.9,3269.25 ccw(c4058.9,3201.15) 4022.9,3258.95 4022.9,3303.54 ccw(c4058.9,3361.34)
  region net IN-: 4040,3923.65 4030,3923.65 4029.91,3924.79 4029.66,3925.92 4028.75,3928.14 4027.47,3930.21 4025.99,3932.06 4044.01,3932.06 4042.53,3930.21 4041.25,3928.14 4040.34,3925.92 4040.09,3924.79
  region net $1N3732: 4009.77,4552.5 4009.77,4562.5 ccw(c4009.77,4581.25) 4024.77,4570 4024.77,4545 ccw(c4009.77,4533.75)
  region net OFFSET2: 4006.22,3674.87 3996.22,3674.87 3996.13,3676.01 3995.88,3677.15 3994.97,3679.36 3993.69,3681.43 3992.22,3683.28 4010.23,3683.28 4008.76,3681.43 4007.47,3679.36 4006.57,3677.15 4006.31,3676.01
  region net $1N3732: 3990.79,3397.28 4000.79,3397.28 ccw(c4019.54,3397.28) 4008.29,3382.28 3983.29,3382.28 ccw(c3972.04,3397.28)
  region net VCC-: 3977.74,3246.22 3955.96,3258.38 ccw(c3905.04,3296.57) 3968.68,3296.57 4015.92,3258.95 ccw(c4015.92,3195.31)
  region net $1N3732: 3953.68,3354.99 3953.68,3364.99 ccw(c3953.68,3383.74) 3968.68,3372.49 3968.68,3347.49 ccw(c3953.68,3336.24)
  region net $1N3732: 3935,3749.05 cw(c3985,3749.05) 3945,3779.05 3930,3784.05 3925,3779.05 3925,3749.05
  region net VCC+: 3928.87,5022.55 3928.87,4998.55 ccw(c3928.87,4906.03) 3892.87,4991.26 3892.87,5029.84 ccw(c3928.87,5115.07)
  region net OFFSET1: 3903.12,3653.95 3908.55,3634.38 ccw(c3886.47,3612.3) 3895.23,3642.27 3895.23,3667.27 ccw(c3925.2,3676.03)
  region net $1N519: 3910.23,4570 3910.23,4560 ccw(c3910.23,4541.25) 3895.23,4552.5 3895.23,4577.5 ccw(c3910.23,4588.75)
  region net $1N3714: 3883.65,3800 3883.65,3810 3884.79,3810.09 3885.92,3810.34 3888.14,3811.25 3890.21,3812.53 3892.06,3814.01 3892.06,3795.99 3890.21,3797.47 3888.14,3798.75 3885.92,3799.66 3884.79,3799.91
  region net $1N1844: 4009.77,4735 4009.77,4745 ccw(c4009.77,4763.75) 4024.77,4752.5 4024.77,4727.5 ccw(c4009.77,4716.25)
  region net $1N1844: 3676.35,4745 3676.35,4735 3675.21,4734.91 3674.08,4734.66 3671.86,4733.75 3669.79,4732.47 3667.94,4730.99 3667.94,4749.01 3669.79,4747.53 3671.86,4746.25 3674.08,4745.34 3675.21,4745.09
  region net $1N3732: 3865,3445.16 3855,3445.16 ccw(c3836.25,3445.16) 3847.5,3460.16 3872.5,3460.16 ccw(c3883.75,3445.16)
  region net $1N3714: 3855,3890.16 3845,3890.16 ccw(c3826.25,3890.16) 3837.5,3905.16 3862.5,3905.16 ccw(c3873.75,3890.16)
  region net $1N519: 3841.81,4863.74 3851.81,4863.74 ccw(c3870.56,4863.74) 3859.31,4848.74 3834.31,4848.74 ccw(c3823.06,4863.74)
  region net $1N519: 3851.81,4885.71 3841.81,4885.71 ccw(c3823.06,4885.71) 3834.31,4900.71 3859.31,4900.71 ccw(c3870.56,4885.71)
  region net $1N1834: 3841.61,4322.26 3851.61,4322.26 ccw(c3870.36,4322.26) 3859.11,4307.26 3834.11,4307.26 ccw(c3822.86,4322.26)
  region net $1N1834: 3851.61,4353.65 3841.61,4353.65 3841.52,4354.79 3841.27,4355.92 3840.36,4358.14 3839.07,4360.21 3837.6,4362.06 3855.62,4362.06 3854.14,4360.21 3852.86,4358.14 3851.95,4355.92 3851.7,4354.79
  region net IN+: 3851.61,4440.16 3841.61,4440.16 ccw(c3822.86,4440.16) 3834.11,4455.16 3859.11,4455.16 ccw(c3870.36,4440.16)
  region net $1N1834: 3851.61,4621.26 3841.61,4621.26 ccw(c3822.86,4621.26) 3834.11,4636.26 3859.11,4636.26 ccw(c3870.36,4621.26)
  region net $1N1834: 3841.61,4621.35 3851.61,4621.35 3851.7,4620.21 3851.95,4619.08 3852.86,4616.86 3854.14,4614.79 3855.62,4612.94 3837.6,4612.94 3839.07,4614.79 3840.36,4616.86 3841.27,4619.08 3841.52,4620.21
  region net VCC-: 3839.3,3203.25 3839.3,3179.25 ccw(c3839.3,3111.15) 3803.3,3168.95 3803.3,3213.54 ccw(c3839.3,3271.34)
  region net OFFSET1: 3790.93,3665.55 3791.75,3655.55 3790.62,3655.46 3789.47,3655.19 3787.23,3654.24 3785.15,3652.9 3783.35,3651.37 3782.52,3669.36 3784.41,3667.96 3786.47,3666.74 3788.66,3665.88 3789.79,3665.64
  region net OFFSET1: 3782.99,3655.55 3782.99,3665.55 ccw(c3782.99,3684.3) 3797.99,3673.05 3797.99,3648.05 ccw(c3782.99,3636.8)
  region net OFFSET1: 3771.19,3307.28 3781.19,3307.28 ccw(c3799.94,3307.28) 3788.69,3292.28 3763.69,3292.28 ccw(c3752.44,3307.28)
  region net $1N1839: 3785.75,4100 3785.75,4110 ccw(c3785.75,4128.75) 3800.75,4117.5 3800.75,4092.5 ccw(c3785.75,4081.25)
  region net $1N519: 3782.99,4560 3782.99,4570 ccw(c3782.99,4588.75) 3797.99,4577.5 3797.99,4552.5 ccw(c3782.99,4541.25)
  region net $1N519: 3687.01,4570 3687.01,4560 ccw(c3687.01,4541.25) 3672.01,4552.5 3672.01,4577.5 ccw(c3687.01,4588.75)
  region net $1N1844: 3782.99,3565 3782.99,3575 ccw(c3782.99,3593.75) 3797.99,3582.5 3797.99,3557.5 ccw(c3782.99,3546.25)
  region net $1N1844: 3687.01,3575 3687.01,3565 ccw(c3687.01,3546.25) 3672.01,3557.5 3672.01,3582.5 ccw(c3687.01,3593.75)
  region net $1N519: 3681.89,4925 3681.89,4915 ccw(c3681.89,4896.25) 3666.89,4907.5 3666.89,4932.5 ccw(c3681.89,4943.75)
  region net $1N519: 3785.75,4915 3785.75,4925 ccw(c3785.75,4943.75) 3800.75,4932.5 3800.75,4907.5 ccw(c3785.75,4896.25)
  region net $1N1844: 3681.89,4020 3681.89,4010 ccw(c3681.89,3991.25) 3666.89,4002.5 3666.89,4027.5 ccw(c3681.89,4038.75)
  region net $1N1844: 3785.75,4010 3785.75,4020 ccw(c3785.75,4038.75) 3800.75,4027.5 3800.75,4002.5 ccw(c3785.75,3991.25)
  region net $1N1839: 3669.3,4227.74 3659.3,4227.74 ccw(c3640.55,4227.74) 3651.8,4242.74 3676.8,4242.74 ccw(c3688.05,4227.74)
  region net $1N1844: 3618.39,3655.87 3628.39,3655.87 ccw(c3647.14,3655.87) 3635.89,3640.87 3610.89,3640.87 ccw(c3599.64,3655.87)
  region net $1N1844: 3628.39,3929.13 3618.39,3929.13 ccw(c3599.64,3929.13) 3610.89,3944.13 3635.89,3944.13 ccw(c3647.14,3929.13)
  region net $1N519: 3615.83,4650.87 3625.83,4650.87 ccw(c3644.58,4650.87) 3633.33,4635.87 3608.33,4635.87 ccw(c3597.08,4650.87)
  region net $1N519: 3625.83,4834.13 3615.83,4834.13 ccw(c3597.08,4834.13) 3608.33,4849.13 3633.33,4849.13 ccw(c3644.58,4834.13)
  region net $1N1844: 3569.46,4083.46 3575.9,4091.17 ccw(c3591.81,4112.38) 3591.81,4085.87 3574.77,4067.55 ccw(c3548.25,4067.55)
  region net $1N1844: 3560,4353.65 3550,4353.65 3549.91,4354.79 3549.66,4355.92 3548.75,4358.14 3547.47,4360.21 3545.99,4362.06 3564.01,4362.06 3562.53,4360.21 3561.25,4358.14 3560.34,4355.92 3560.09,4354.79
  region net IN+: 3152.8,4585 3160.3,4575 3155.3,4574.76 3151.05,4574.07 3147.44,4572.95 3144.4,4571.43 3141.82,4569.55 3139.62,4567.33 3137.7,4564.81 3135.98,4562.02 3132.75,4555.73 3129.22,4548.72 3127.11,4545.01 3124.64,4541.21 3121.74,4537.35 3118.3,4533.46 3110.8,4623.15 3113.21,4621.15 3115.63,4618.77 3118.07,4616.09 3120.52,4613.17 3130.61,4600.5 3133.22,4597.44 3135.87,4594.56 3138.56,4591.93 3141.3,4589.62 3144.09,4587.7 3146.93,4586.25 3149.83,4585.32 3151.31,4585.08
Bottom Layer:
  region net OUT: 6143.31,4163 6143.31,4187 6147.69,4187.19 6151.51,4187.74 6154.85,4188.63 6157.77,4189.84 6160.34,4191.33 6162.63,4193.09 6164.71,4195.09 6166.65,4197.31 6170.38,4202.31 6174.37,4207.88 6176.63,4210.83 6179.16,4213.84 6182.03,4216.91 6185.31,4220 6185.31,4130 6182.03,4133.09 6179.16,4136.16 6176.63,4139.17 6174.37,4142.12 6170.38,4147.69 6166.65,4152.69 6164.71,4154.91 6162.63,4156.91 6160.34,4158.67 6157.77,4160.16 6154.85,4161.37 6151.51,4162.26 6147.69,4162.81
  region net $1N1895: 5612.2,4100 5612.2,4090 ccw(c5612.2,4071.25) 5597.2,4082.5 5597.2,4107.5 ccw(c5612.2,4118.75)
  region net $1N2546: 5538.75,4198.75 5544.64,4207 ccw(c5560.55,4228.21) 5560.55,4201.69 5544.06,4182.84 ccw(c5517.54,4182.84)
  region net $1N1895: 5544.64,4062.14 5538.75,4070.39 ccw(c5517.54,4086.3) 5544.06,4086.3 5560.55,4067.44 ccw(c5560.55,4040.93)
  region net $1N2546: 5544.64,4140.88 5538.75,4149.13 ccw(c5517.54,4165.04) 5544.06,4165.04 5560.55,4146.18 ccw(c5560.55,4119.67)
  region net $1N2546: 5452.74,4101.46 5452.74,4091.46 ccw(c5452.74,4072.71) 5437.74,4083.96 5437.74,4108.96 ccw(c5452.74,4120.21)
  region net $1N2565: 5368.52,4170.2 5368.52,4180.2 ccw(c5368.52,4198.95) 5383.52,4187.7 5383.52,4162.7 ccw(c5368.52,4151.45)
  region net $1N2565: 5353.32,4180.2 5353.32,4170.2 5352.18,4170.11 5351.05,4169.85 5348.83,4168.95 5346.76,4167.66 5344.92,4166.19 5344.92,4184.2 5346.76,4182.73 5348.83,4181.45 5351.05,4180.54 5352.18,4180.29
  region net $1N2565: 5307.74,4180.2 5307.74,4170.2 ccw(c5307.74,4151.45) 5292.74,4162.7 5292.74,4187.7 ccw(c5307.74,4198.95)
  region net $1N2565: 5320.62,4170.2 5320.62,4180.2 5321.76,4180.29 5322.9,4180.54 5325.11,4181.45 5327.18,4182.73 5329.03,4184.2 5329.03,4166.19 5327.18,4167.66 5325.11,4168.95 5322.9,4169.85 5321.76,4170.11
  region net $1N2520: 5233.22,4123.06 5245.1,4125.32 ccw(c5261.01,4146.53) 5261.01,4120.01 5238.52,4107.15 ccw(c5212.01,4107.15)
  region net $1N1895: 5195,4075 cw(c5145,4075) 5185,4045 5200.02,4040 5215,4045 cw(c5255,4075) 5205,4075
  region net $1N1895: 5170.23,4045 5170.23,4035 ccw(c5170.23,4016.25) 5155.23,4027.5 5155.23,4052.5 ccw(c5170.23,4063.75)
  region net $1N2520: 5170.23,4370 5170.23,4360 ccw(c5170.23,4341.25) 5155.23,4352.5 5155.23,4377.5 ccw(c5170.23,4388.75)
  region net $1N1895: 5169.45,4460.55 5169.45,4450.55 ccw(c5169.45,4433.32) 5155.23,4443.05 5155.23,4468.05 ccw(c5169.45,4477.78)
  region net $1N2487: 5142.29,3833.62 5142.29,3823.62 ccw(c5142.29,3804.87) 5127.29,3816.12 5127.29,3841.12 ccw(c5142.29,3852.37)
  region net VCC-: 5049.45,3937.45 5049.45,3961.45 ccw(c5049.45,3970.09) 5057.99,3968.74 5057.99,3930.16 ccw(c5049.45,3928.81)
  region net $1N2501: 5042.99,4125.55 5042.99,4135.55 ccw(c5042.99,4154.3) 5057.99,4143.05 5057.99,4118.05 ccw(c5042.99,4106.8)
  region net $1N2487: 5086.5,4247.27 5066.93,4241.84 ccw(c5044.85,4263.92) 5074.82,4255.16 5099.82,4255.16 ccw(c5108.58,4225.19)
  region net VCC-: 5014.26,3891.72 5038.26,3891.72 ccw(c5106.36,3891.72) 5048.55,3855.72 5003.97,3855.72 ccw(c4946.16,3891.72)
  region net $1N2520: 4947.01,4370 4947.01,4360 ccw(c4947.01,4341.25) 4932.01,4352.5 4932.01,4377.5 ccw(c4947.01,4388.75)
  region net $1N2520: 5042.99,4360 5042.99,4370 ccw(c5042.99,4388.75) 5057.99,4377.5 5057.99,4352.5 ccw(c5042.99,4341.25)
  region net $1N1895: 4945.33,4109.01 4939.9,4089.44 ccw(c4961.98,4067.36) 4932.01,4076.12 4932.01,4101.12 ccw(c4923.25,4131.09)
  region net VCC-: 5003.4,3788.78 4991.24,3810.56 ccw(c4940.33,3848.75) 5003.97,3848.75 5041.58,3801.51 ccw(c5041.58,3737.87)
  region net $1N2520: 4819.77,4360 4819.77,4370 ccw(c4819.77,4388.75) 4834.77,4377.5 4834.77,4352.5 ccw(c4819.77,4341.25)
  region net $1N2269: 4853.65,4585 4853.65,4595 4854.79,4595.09 4855.92,4595.34 4858.14,4596.25 4860.21,4597.53 4862.06,4599.01 4862.06,4580.99 4860.21,4582.47 4858.14,4583.75 4855.92,4584.66 4854.79,4584.91
  region net $1N1895: 4821.35,4095 4821.35,4085 4820.21,4084.91 4819.08,4084.66 4816.86,4083.75 4814.79,4082.47 4812.94,4080.99 4812.94,4099.01 4814.79,4097.53 4816.86,4096.25 4819.08,4095.34 4820.21,4095.09
  region net $1N2546: 4709.05,4560 4709.05,4550 ccw(c4709.05,4531.25) 4694.05,4542.5 4694.05,4567.5 ccw(c4709.05,4578.75)
  region net $1N2487: 4800,3930 cw(c4800,3980) 4770,3940 4765,3925
  region net VCC+: 4778.3,4481.33 4761.33,4498.3 4771.51,4508.49 4788.49,4491.51
  region net VCC-: 4713,3156.69 4737,3156.69 4737.19,3152.31 4737.74,3148.49 4738.63,3145.15 4739.84,3142.23 4741.33,3139.66 4743.09,3137.37 4745.09,3135.29 4747.31,3133.35 4752.31,3129.62 4757.88,3125.63 4760.83,3123.37 4763.84,3120.84 4766.91,3117.97 4770,3114.69 4680,3114.69 4683.09,3117.97 4686.16,3120.84 4689.17,3123.37 4692.12,3125.63 4697.69,3129.62 4702.69,3133.35 4704.91,3135.29 4706.91,3137.37 4708.67,3139.66 4710.16,3142.23 4711.37,3145.15 4712.26,3148.49 4712.81,3152.31
  region net VCC+: 4682.3,5115.33 4665.33,5132.3 4666.77,5134.13 4667.82,5136.31 4668.51,5138.79 4668.9,5141.53 4669.03,5144.47 4668.93,5147.59 4668.24,5154.17 4667.17,5160.91 4666.06,5167.49 4665.26,5173.55 4665.09,5176.28 4665.12,5178.76 4728.76,5115.12 4726.28,5115.09 4723.55,5115.26 4717.49,5116.06 4710.91,5117.17 4704.17,5118.24 4697.59,5118.93 4694.47,5119.03 4691.53,5118.9 4688.79,5118.51 4686.31,5117.82 4684.13,5116.77
  region net VCC+: 4730.05,4476.45 4730.05,4452.45 ccw(c4730.05,4359.93) 4694.05,4445.16 4694.05,4483.74 ccw(c4730.05,4568.97)
  region net $1N2565: 4695.54,4226.54 4691.97,4215.96 ccw(c4676.06,4194.74) 4676.06,4221.26 4690.23,4242.45 ccw(c4716.75,4242.45)
  region net $1N2565: 4689.9,4218.02 4696.98,4225.1 4697.84,4224.35 4698.83,4223.73 4701.03,4222.81 4703.41,4222.25 4705.75,4221.98 4693.02,4209.25 4692.75,4211.59 4692.19,4213.97 4691.27,4216.17 4690.65,4217.16
  region net $1N2269: 4709.05,4650.55 4709.05,4640.55 ccw(c4709.05,4621.8) 4694.05,4633.05 4694.05,4658.05 ccw(c4709.05,4669.3)
  region net $1N2487: 4715.23,3870 4715.23,3860 ccw(c4715.23,3841.25) 4700.23,3852.5 4700.23,3877.5 ccw(c4715.23,3888.75)
  region net $1N2501: 4715.23,3694.45 4715.23,3684.45 ccw(c4715.23,3665.7) 4700.23,3676.95 4700.23,3701.95 ccw(c4715.23,3713.2)
  region net $1N2520: 4705.23,4064.45 4705.23,4054.45 ccw(c4705.23,4035.7) 4690.23,4046.95 4690.23,4071.95 ccw(c4705.23,4083.2)
  region net VCC-: 4647.03,3565.62 4647.03,3541.62 ccw(c4647.03,3491.17) 4611.03,3526.51 4611.03,3580.72 ccw(c4647.03,3616.06)
  region net VCC-: 4713,3469.62 ccw(c4593,3469.62) 4689,3541.62 4721.88,3553.62 4751.26,3541.62 ccw(c4925.9,3469.62) 4737,3469.62
  region net $1N2546: 4586.93,4550 4586.93,4560 ccw(c4586.93,4578.75) 4601.93,4567.5 4601.93,4542.5 ccw(c4586.93,4531.25)
  region net $1N2501: 4587.99,3684.45 4587.99,3694.45 ccw(c4587.99,3713.2) 4602.99,3701.95 4602.99,3676.95 ccw(c4587.99,3665.7)
  region net $1N2546: 4577.99,4145 4577.99,4155 ccw(c4577.99,4173.75) 4592.99,4162.5 4592.99,4137.5 ccw(c4577.99,4126.25)
  region net VCC-: 4565.88,3513.78 4553.72,3535.56 ccw(c4502.81,3573.75) 4566.45,3573.75 4604.06,3526.51 ccw(c4604.06,3462.87)
  region net $1N2520: 4587.99,3775 4587.99,3785 ccw(c4587.99,3803.75) 4602.99,3792.5 4602.99,3767.5 ccw(c4587.99,3756.25)
  region net $1N2520: 4492.01,3785 4492.01,3775 ccw(c4492.01,3756.25) 4477.01,3767.5 4477.01,3792.5 ccw(c4492.01,3803.75)
  region net $1N2520: 4577.99,4040 4577.99,4050 ccw(c4577.99,4068.75) 4592.99,4057.5 4592.99,4040.16 ccw(c4592.99,3330.3)
  region net $1N2501: 4505,3595.72 4515,3595.72 ccw(c4533.75,3595.72) 4522.5,3580.72 4497.5,3580.72 ccw(c4486.25,3595.72)
  region net $1N2546: 4482.01,4155 4482.01,4145 ccw(c4482.01,4126.25) 4467.01,4137.5 4467.01,4162.5 ccw(c4482.01,4173.75)
  region net $1N2546: 4550,4185 cw(c4500,4185) 4540,4155 4555.53,4150 4570,4155 cw(c4610,4185) 4560,4185
  region net $1N2520: 4423.39,3865.87 4433.39,3865.87 ccw(c4452.14,3865.87) 4440.89,3850.87 4415.89,3850.87 ccw(c4404.64,3865.87)
  region net OUT: 4321.23,4447 4321.23,4423 ccw(c4321.23,4336.44) 4285.23,4415.16 4285.23,4453.74 ccw(c4321.23,4546.49)
  region net $1N2546: 4356.45,4080.99 4361.88,4100.56 ccw(c4339.8,4122.64) 4369.77,4113.88 4369.77,4088.88 ccw(c4378.53,4058.91)
  region net $1N2546: 4300.23,4530 4300.23,4520 ccw(c4300.23,4501.25) 4285.23,4512.5 4285.23,4537.5 ccw(c4300.23,4548.75)
  region net $1N2546: 4360.95,4520 4360.95,4530 ccw(c4360.95,4548.75) 4375.95,4537.5 4375.95,4512.5 ccw(c4360.95,4501.25)
  region net OUT: 4248.61,4379.16 4224.61,4379.16 ccw(c4179.61,4379.16) 4206.61,4415.16 4266.61,4415.16 ccw(c4293.61,4379.16)
  region net $1N2679: 4223,4670.84 4247,4670.84 ccw(c4292,4670.84) 4265,4634.84 4205,4634.84 ccw(c4178,4670.84)
  region net OUT: 4227.23,4229.83 4239.39,4208.05 ccw(c4290.3,4169.87) 4226.66,4169.87 4189.05,4217.11 ccw(c4189.05,4280.75)
  region net $1N2520: 4098.07,3559.45 4098.07,3549.45 ccw(c4098.07,3530.7) 4083.07,3541.95 4083.07,3566.95 ccw(c4098.07,3578.2)
  region net OUT: 4192.37,4126.55 4216.37,4126.55 ccw(c4282.19,4126.54) 4227.09,4090.55 4182.5,4090.55 ccw(c4121.78,4126.55)
  region net OUT: 4216.37,4126.89 4192.37,4126.89 ccw(c4124.27,4126.89) 4182.08,4162.89 4226.66,4162.89 ccw(c4284.47,4126.89)
  region net $1N2546: 4223.6,4497.82 4204.03,4492.39 ccw(c4181.95,4514.47) 4211.92,4505.71 4236.92,4505.71 ccw(c4245.68,4475.74)
  region net $1N2679: 4160.55,4603.55 4160.55,4627.55 ccw(c4160.55,4682.82) 4187.99,4634.84 4187.99,4596.26 ccw(c4160.55,4548.28)
  region net VCC-: 4119.07,3657 4119.07,3633 ccw(c4119.07,3540.48) 4083.07,3625.71 4083.07,3664.29 ccw(c4119.07,3749.52)
  region net VCC-: 4180.93,3633 4180.93,3657 ccw(c4180.93,3702) 4216.93,3675 4216.93,3615 ccw(c4180.93,3588)
  region net $1N2679: 4113,4253.11 4137,4253.11 ccw(c4201.78,4253.11) 4147.92,4217.11 4103.34,4217.11 ccw(c4041.11,4253.11)
  region net $1N2714: 4137,4000.33 4113,4000.33 ccw(c4038.25,4000.33) 4103.76,4036.33 4148.35,4036.33 ccw(c4199.78,4000.33)
  region net $1N2679: 4051.23,4741.45 4051.23,4717.45 ccw(c4051.23,4624.93) 4015.23,4710.16 4015.23,4748.74 ccw(c4051.23,4833.97)
  region net $1N2714: 4085.55,3747.55 4085.55,3723.55 ccw(c4095.04,3716.26) 4083.07,3716.26 4083.07,3754.84 ccw(c4095.04,3754.84)
  region net IN-: 4043.02,3955.1 4050.1,3948.02 4049.35,3947.16 4048.73,3946.17 4047.81,3943.97 4047.25,3941.59 4046.98,3939.25 4034.25,3951.98 4036.59,3952.25 4038.97,3952.81 4041.17,3953.73 4042.16,3954.35
  region net $1N2546: 4008.39,4610.87 4018.39,4610.87 ccw(c4037.14,4610.87) 4025.89,4595.87 4000.89,4595.87 ccw(c3989.64,4610.87)
  region net $1N2546: 4029.45,4915.55 4029.45,4905.55 ccw(c4029.45,4888.32) 4015.23,4898.05 4015.23,4923.05 ccw(c4029.45,4932.78)
  region net OFFSET2: 4000,3944.16 3990,3944.16 3989.9,3946.46 3989.61,3948.45 3989.13,3950.16 3988.5,3951.62 3987.7,3952.89 3986.77,3954 3984.53,3955.9 3978.93,3959.55 3975.76,3961.95 3974.14,3963.43 3972.5,3965.16 4017.5,3965.16 4015.86,3963.43 4014.24,3961.95 4011.07,3959.55 4005.47,3955.9 4003.23,3954 4002.3,3952.89 4001.5,3951.62 4000.87,3950.16 4000.39,3948.45 4000.1,3946.46
  region net VCC-: 3954.95,3633 3954.95,3657 ccw(c3954.95,3749.52) 3990.95,3664.29 3990.95,3625.71 ccw(c3954.95,3540.48)
  region net OFFSET2: 3985.95,3697.76 3991.76,3706.08 3992.63,3705.35 3993.64,3704.73 3995.95,3703.82 3998.42,3703.33 4000.79,3703.22 3989.37,3689.3 3988.93,3691.58 3988.28,3693.85 3987.32,3695.95 3986.69,3696.9
  region net $1N2546: 4077.43,4779.53 4108.13,4780 4110,4790 cw(c4110,4820) 4080,4820 4070,4818.9 cw(c4040,4818.9) 4040,4788.9
  region net $1N3714: 3968.54,3801.46 3961.46,3808.54 3962.14,3809.34 3962.58,3810.14 3962.85,3810.96 3962.97,3811.81 3963.02,3815.75 3975.75,3803.02 3971.81,3802.97 3970.96,3802.85 3970.14,3802.58 3969.34,3802.14
  region net VCC-: 3954.16,4073 3954.16,4097 3957.09,4097.24 3959.95,4097.9 3962.72,4098.94 3965.4,4100.28 3967.99,4101.87 3970.48,4103.64 3975.16,4107.5 3975.16,4062.5 3970.48,4066.36 3967.99,4068.13 3965.4,4069.72 3962.72,4071.06 3959.95,4072.1 3957.09,4072.76
  region net $1N3714: 3916.35,3810 3916.35,3800 3915.21,3799.91 3914.08,3799.66 3911.86,3798.75 3909.79,3797.47 3907.94,3795.99 3907.94,3814.01 3909.79,3812.53 3911.86,3811.25 3914.08,3810.34 3915.21,3810.09
  region net OFFSET1: 3958.18,4175 3950.68,4185 3952.84,4185.11 3954.76,4185.42 3956.48,4185.93 3958.01,4186.62 3959.4,4187.48 3960.65,4188.48 3961.8,4189.63 3962.87,4190.9 3964.88,4193.76 3966.89,4196.95 3969.09,4200.36 3971.68,4203.88 3979.18,4159.51 3976.79,4161.29 3974.3,4163.56 3969.1,4168.71 3966.41,4171.12 3963.69,4173.12 3962.32,4173.9 3960.94,4174.49 3959.56,4174.87
  region net VCC-: 3962,3561 cw(c4034,3561) 4034,3633 3946.73,3656.58 3894.8,3707.17 3936.2,3633.62 3938,3561.17
  region net VCC+: 3881.99,4808 3881.99,4832 ccw(c3881.99,4924.52) 3917.99,4839.29 3917.99,4800.71 ccw(c3881.99,4715.48)
  region net VCC+: 3828.01,4832 3828.01,4808 ccw(c3828.01,4763) 3792.01,4790 3792.01,4850 ccw(c3828.01,4877)
  region net $1N1834: 3841.61,4386.35 3851.61,4386.35 3851.7,4385.21 3851.95,4384.08 3852.86,4381.86 3854.14,4379.79 3855.62,4377.94 3837.6,4377.94 3839.07,4379.79 3840.36,4381.86 3841.27,4384.08 3841.52,4385.21
  region net $1N1834: 3851.61,4588.65 3841.61,4588.65 3841.52,4589.79 3841.27,4590.92 3840.36,4593.14 3839.07,4595.21 3837.6,4597.06 3855.62,4597.06 3854.14,4595.21 3852.86,4593.14 3851.95,4590.92 3851.7,4589.79
  region net VCC+: 3820.1,4913.69 3810.95,4870.59 ccw(c3863.94,4817.6) 3792.01,4838.62 3792.01,4890.87 ccw(c3695.91,5037.88)
  region net OFFSET1: 3770,3676.35 3780,3676.35 3780.09,3675.21 3780.34,3674.08 3781.25,3671.86 3782.53,3669.79 3784.01,3667.94 3765.99,3667.94 3767.47,3669.79 3768.75,3671.86 3769.66,3674.08 3769.91,3675.21
  region net $1N1844: 3643.65,4735 3643.65,4745 3644.79,4745.09 3645.92,4745.34 3648.14,4746.25 3650.21,4747.53 3652.06,4749.01 3652.06,4730.99 3650.21,4732.47 3648.14,4733.75 3645.92,4734.66 3644.79,4734.91
  region net $1N1844: 3550,4386.35 3560,4386.35 3560.09,4385.21 3560.34,4384.08 3561.25,4381.86 3562.53,4379.79 3564.01,4377.94 3545.99,4377.94 3547.47,4379.79 3548.75,4381.86 3549.66,4384.08 3549.91,4385.21
  region net IN-: 3156.69,3680 3156.69,3670 3155.27,3669.91 3153.85,3669.66 3151.01,3668.69 3148.17,3667.17 3145.34,3665.16 3142.53,3662.74 3139.74,3659.98 3136.99,3656.96 3134.27,3653.75 3128.97,3647.05 3123.91,3640.47 3119.13,3634.59 3116.86,3632.1 3114.69,3630 3114.69,3720 3116.86,3717.9 3119.13,3715.41 3123.91,3709.53 3128.97,3702.95 3134.27,3696.25 3136.99,3693.04 3139.74,3690.02 3142.53,3687.26 3145.34,3684.84 3148.17,3682.83 3151.01,3681.31 3153.85,3680.34 3155.27,3680.09

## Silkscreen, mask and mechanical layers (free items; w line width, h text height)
Top Silkscreen Layer:
  the board outline again, w30
  text "+VCC" at 4690,5095 h60 r270
  text "+" at 3155,4520 h120
  text "OUT" at 6040,4145 h60
  text "-" at 3154.99,3615 h120
  text "uA741" at 3940,3515 h150
  text "-VCC" at 4695,3315 h60 r270
Bottom Silkscreen Layer:
  the board outline again, w30
  text "+VCC" at 4690,4940 h60 r270
  text "+" at 3252,4617 h120 r90
  text "OUT" at 6150,4145 h60
  text "-" at 3225,3615 h120
  text "-VCC" at 4690,3145 h60 r270
  text "uA741" at 3530,3110 h120 r270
